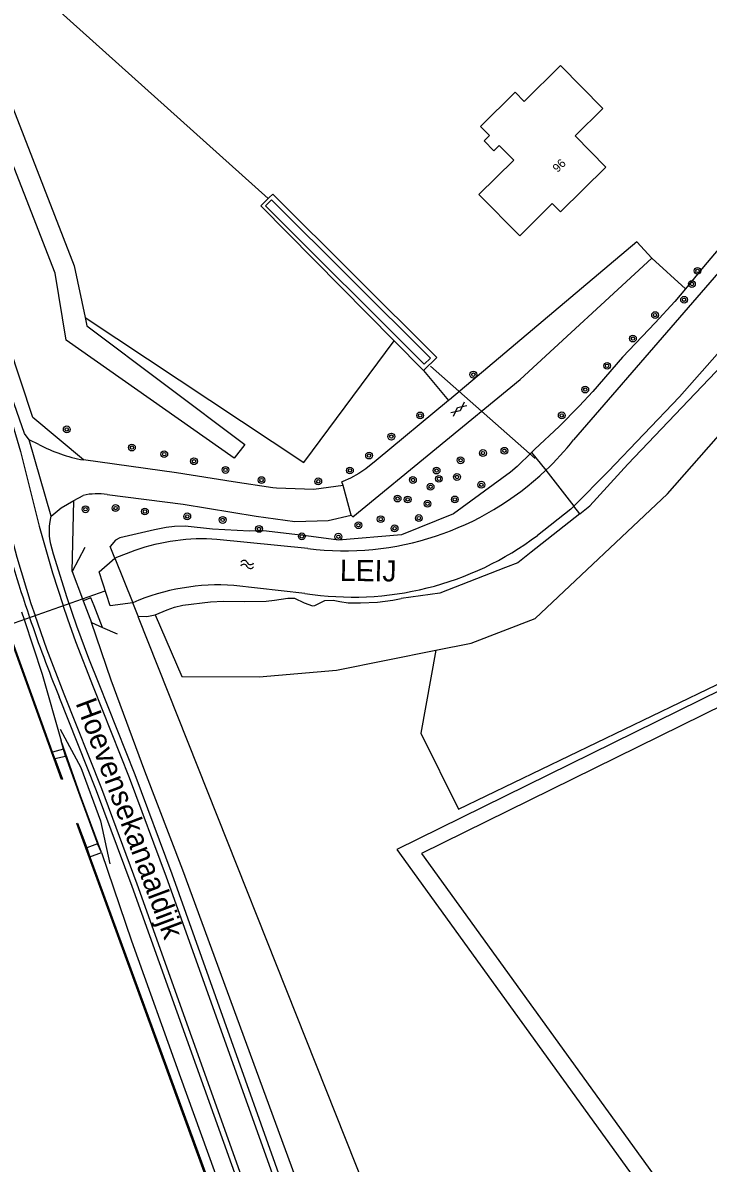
# Model space of a CAD drawing. Extents: x 135990 to 139000, y 393500 to 396000.
# Drawn here: x 136194.1 to 136274.9, y 395713.3 to 395847.7 of the extents above; entities that cross this region are included whole.
import ezdxf

# ---------------------------------------------------------------- set-up
doc = ezdxf.new("R2010")
doc.units = 0
for name, color, linetype in [('gg-afsc-hekwerk', 7, 'Continuous'), ('gg-afsc-muur', 7, 'Continuous'), ('gg-anno-huisnummerreeks BGT', 7, 'Continuous'), ('gg-anno-naam water', 7, 'Continuous'), ('gg-anno-openbare ruimte label', 7, 'Continuous'), ('gg-bbg-hoofdgebouw', 7, 'Continuous'), ('gg-knt-bovenkant onderkant talud', 7, 'Continuous'), ('gg-knt-bronhoudergrens', 7, 'Continuous'), ('gg-knt-verharding', 7, 'Continuous'), ('gg-knt-verharding nz', 7, 'Continuous'), ('gg-kntw-bovenkant insteek waterloop', 7, 'Continuous'), ('gg-kntw-waterlijn', 7, 'Continuous'), ('gg-kwrk-duiker nz buis', 7, 'Continuous'), ('gt-grn-groengrens', 7, 'Continuous'), ('gt-symb-boom', 7, 'Continuous'), ('gt-symb-gesloten verharding', 7, 'Continuous'), ('gt-symb-watersymbool', 7, 'Continuous'), ('gx-grn-maaiveld', 7, 'Continuous')]:
    doc.layers.add(name, color=color, linetype=linetype)

# ---------------------------------------------------------------- blocks, each defined once
blk = doc.blocks.new('gt0-BOOM')
at = {"layer": 'gt-symb-boom'}
for radius in [0.4, 0.2]:
    blk.add_circle((0, 0), radius, dxfattribs=at)
blk = doc.blocks.new('gt0-GESVH1')
at = {"layer": 'gt-symb-gesloten verharding'}
for p, q in [((-0.99, -0.26), (0.01, 0.24)), ((0.01, -0.26), (-0.99, 0.24)), ((0.01, 0.24), (1.01, -0.26)), ((1.01, 0.24), (0.01, -0.26))]:
    blk.add_line(p, q, dxfattribs=at)
blk = doc.blocks.new('gt0-WA')
at = {"layer": 'gt-symb-watersymbool'}
for centre, start, end in [((-0.32, 0.02), 28.0725, 151.9275), ((0.43, 0.42), 208.0725, 331.9275), ((-0.32, -0.43), 28.0725, 151.9275), ((0.43, -0.03), 208.0725, 331.9275)]:
    blk.add_arc(centre, 0.425, start, end, dxfattribs=at)

msp = doc.modelspace()

# ---------------------------------------------------------------- linework, layer by layer
at = {"layer": 'gg-afsc-hekwerk'}
for p, q in [((136201.427, 395785.836), (136199.906, 395783.029)), ((136199.906, 395783.029), (136201.129, 395779.798)), ((136199.906, 395783.029), (136201.129, 395779.798)), ((136201.129, 395779.798), (136201.228, 395779.538)), ((136201.129, 395779.798), (136201.228, 395779.538)), ((136201.228, 395779.538), (136202.196, 395776.981)), ((136202.196, 395776.981), (136203.482, 395776.416)), ((136202.196, 395776.981), (136203.482, 395776.416)), ((136203.482, 395776.416), (136205.21, 395775.656))]:
    msp.add_line(p, q, dxfattribs=at)
msp.add_lwpolyline([(136198.493, 395764.421), (136200.941, 395759.895), (136203.276, 395753.629), (136204.365, 395748.54)], dxfattribs=at)
at = {"layer": 'gg-afsc-muur'}
msp.add_line((136204.961, 395784.588), (136207.057, 395779.333), dxfattribs=at)
at = {"layer": 'gg-bbg-hoofdgebouw'}
msp.add_lwpolyline([(136248.077, 395835.46), (136252.165, 395839.498), (136253.221, 395838.43), (136257.49, 395842.675), (136262.501, 395837.597), (136259.215, 395834.354), (136262.843, 395830.681), (136257.497, 395825.405), (136256.523, 395826.382), (136252.687, 395822.571), (136247.885, 395827.441), (136252.008, 395831.49), (136250.285, 395833.229), (136249.652, 395832.602), (136248.507, 395833.769), (136249.135, 395834.391), (136248.077, 395835.46)], dxfattribs=at)
at = {"layer": 'gg-knt-bovenkant onderkant talud'}
msp.add_line((136199.906, 395783.029), (136200.101, 395791.389), dxfattribs=at)
for points in [[(136201.244, 395796.154), (136195.273, 395801.183), (136192.468, 395809.72), (136176.417, 395851.255), (136158.526, 395900.168), (136141.395, 395948.185), (136130.007, 395978.958)], [(136249.062, 395655.202), (136232.635, 395694.301), (136212.963, 395747.797), (136208.496, 395759.474), (136204.504, 395770.218), (136202.196, 395776.981)]]:
    msp.add_lwpolyline(points, dxfattribs=at)
at = {"layer": 'gg-knt-bronhoudergrens'}
msp.add_line((136191.248, 395855.527), (136223.025, 395826.98), dxfattribs=at)
for points in [[(136201.434, 395812.944), (136227.231, 395795.863), (136237.869, 395810.202)], [(136242.796, 395773.719), (136246.968, 395774.553), (136254.509, 395777.464), (136270.119, 395792.148), (136287.348, 395811.748)], [(136242.796, 395773.719), (136241.05, 395763.965), (136245.473, 395754.982), (136320.519, 395791.13)], [(136209.693, 395777.907), (136212.853, 395770.62), (136221.965, 395770.584), (136226.529, 395770.981), (136231.093, 395771.378), (136242.796, 395773.719)]]:
    msp.add_lwpolyline(points, dxfattribs=at)
at = {"layer": 'gg-knt-verharding'}
for p, q in [((136195.981, 395797.97), (136194.84, 395798.55)), ((136231.863, 395793.154), (136231.717, 395793.584)), ((136232.832, 395789.659), (136231.863, 395793.154)), ((136200.101, 395791.389), (136201.233, 395791.976)), ((136232.832, 395789.659), (136233.002, 395789.452))]:
    msp.add_line(p, q, dxfattribs=at)
for points in [[(136194.84, 395798.55), (136194.304, 395799.262), (136191.281, 395807.835), (136175.523, 395851.013), (136140.515, 395947.835), (136125.623, 395988.445)], [(136268.273, 395819.957), (136266.5, 395821.879), (136244.401, 395803.251), (136244.305, 395803.171)], [(136233.002, 395789.452), (136252.75, 395805.638), (136268.273, 395819.957)], [(136244.305, 395803.171), (136235.76, 395796.082), (136234.529, 395795.127), (136233.707, 395794.558), (136232.739, 395794.007), (136231.828, 395793.61), (136231.717, 395793.584)], [(136224.004, 395792.838), (136223.571, 395792.853), (136218.893, 395793.581), (136212.228, 395794.652), (136201.244, 395796.154)], [(136231.863, 395793.154), (136228.41, 395792.682), (136224.004, 395792.838)], [(136197.449, 395789.539), (136198.629, 395790.531), (136200.101, 395791.389)], [(136204.043, 395792.076), (136213.004, 395790.931), (136221.629, 395789.529), (136226.189, 395788.889), (136230.119, 395789.015), (136232.832, 395789.659)], [(136203.093, 395769.73), (136201.887, 395772.749), (136200.474, 395776.558), (136199.334, 395779.89), (136197.739, 395785.068), (136197.418, 395786.215), (136197.333, 395786.64), (136197.262, 395787.176), (136197.233, 395787.825), (136197.256, 395788.366), (136197.318, 395788.903), (136197.399, 395789.328), (136197.449, 395789.539)], [(136244.295, 395656.286), (136230.86, 395693.582), (136211.713, 395747.336), (136207.367, 395759.044), (136203.093, 395769.73)], [(136255.708, 395609.808), (136239.744, 395654.526), (136226.317, 395691.893), (136206.997, 395745.883), (136202.792, 395757.151), (136198.369, 395768.24)]]:
    msp.add_lwpolyline(points, dxfattribs=at)
for centre, radius, start, end in [((136204.751, 395814.854), 19.026, 242.54952, 259.37645), ((136202.886, 395785.05), 7.121, 80.65151, 103.42476), ((136373.454, 395838.52), 188.663, 194.92704, 198.83878), ((136373.233, 395838.428), 188.424, 198.83382, 201.86986)]:
    msp.add_arc(centre, radius, start, end, dxfattribs=at)
at = {"layer": 'gg-knt-verharding nz'}
msp.add_line((136197.449, 395789.539), (136194.84, 395798.55), dxfattribs=at)
for points in [[(136116.757, 396000), (136121.671, 395987.179), (136136.571, 395946.56), (136153.867, 395898.856), (136171.516, 395849.993), (136187.438, 395805.778), (136189.89, 395798.04), (136191.937, 395790.186), (136193.392, 395784.681), (136195.054, 395779.234), (136195.542, 395777.827)], [(136120.537, 396000), (136125.042, 395988.226), (136139.915, 395947.719), (136157.35, 395899.595), (136190.76, 395807.111), (136192.059, 395803.156), (136193.814, 395797.163), (136196.045, 395788.338), (136197.62, 395782.842), (136198.877, 395779.004)], [(136256.275, 395610.025), (136240.32, 395654.726), (136226.925, 395692.057), (136207.584, 395746.156), (136203.424, 395757.41), (136198.987, 395768.549), (136196.919, 395773.855), (136195.542, 395777.827)], [(136259.572, 395611.284), (136243.654, 395655.964), (136230.221, 395693.319), (136211.055, 395746.99), (136206.688, 395758.699), (136202.442, 395769.391), (136200.364, 395774.717), (136199.399, 395777.408), (136198.877, 395779.004)]]:
    msp.add_lwpolyline(points, dxfattribs=at)
at = {"layer": 'gg-kntw-bovenkant insteek waterloop'}
for p, q in [((136237.869, 395810.202), (136241.337, 395806.692)), ((136220.261, 395798), (136219.003, 395796.356))]:
    msp.add_line(p, q, dxfattribs=at)
for points in [[(136332.359, 395875.615), (136329.962, 395873.177), (136323.008, 395866.952), (136318.207, 395862.493), (136316.111, 395860.371), (136309.067, 395853.686), (136301.51, 395846.687), (136295.745, 395842.008), (136293.093, 395839.723), (136290.454, 395836.727), (136287.413, 395833.419), (136284.119, 395830.106), (136275.654, 395820.442), (136274.363, 395818.915), (136272.255, 395816.315)], [(136219.003, 395796.356), (136199.198, 395810.289), (136197.929, 395818.163), (136186.924, 395846.364), (136186.411, 395848.506), (136187.663, 395849.065)], [(136188.363, 395849.377), (136189.262, 395846.982), (136200.173, 395819.057), (136201.434, 395812.944)], [(136223.025, 395826.98), (136222.147, 395826.112), (136237.869, 395810.202)], [(136241.337, 395806.692), (136242.898, 395808.235), (136223.584, 395827.504), (136223.133, 395827.086), (136223.025, 395826.98)], [(136201.434, 395812.944), (136201.636, 395811.964), (136220.261, 395798)], [(136312.713, 395786.068), (136312.21, 395786.661), (136238.189, 395750.233), (136287.33, 395682.257), (136289.018, 395683.478)], [(136312.713, 395786.068), (136312.541, 395784.933), (136241.094, 395749.771), (136289.018, 395683.478)], [(136209.693, 395777.907), (136211.107, 395778.49), (136211.989, 395778.807), (136212.959, 395779.032), (136216.244, 395779.44), (136217.767, 395779.498), (136220.288, 395779.473), (136222.791, 395779.522), (136223.787, 395779.612), (136225.337, 395779.876), (136226.131, 395779.85), (136227.289, 395779.299), (136228.269, 395778.977), (136228.548, 395779.001), (136229.704, 395779.608), (136230.679, 395779.635), (136231.466, 395779.461), (136232.475, 395779.33), (136233.932, 395779.316), (136235.93, 395779.398), (136237.74, 395779.623), (136238.72, 395779.824)], [(136207.685, 395777.758), (136208.721, 395777.691), (136209.693, 395777.907)]]:
    msp.add_lwpolyline(points, dxfattribs=at)
at = {"layer": 'gg-kntw-waterlijn'}
for p, q in [((136223.427, 395826.815), (136242.164, 395808.152)), ((136227.713, 395785.706), (136216.995, 395786.794)), ((136207.324, 395785.481), (136204.961, 395784.588)), ((136227.362, 395780.43), (136218.999, 395781.372))]:
    msp.add_line(p, q, dxfattribs=at)
for points in [[(136334.154, 395875.239), (136314.263, 395856.43), (136289.01, 395832.551), (136283.009, 395826.197), (136259.042, 395798.523)], [(136223.427, 395826.815), (136222.699, 395826.125), (136241.437, 395807.461), (136242.164, 395808.152)]]:
    msp.add_lwpolyline(points, dxfattribs=at)
for centre, radius, start, end in [((136233.002, 395816.22), 36.231, 261.04453, 306.96306), ((136215.305, 395762.967), 23.887, 85.94352, 109.51966), ((136217.274, 395755.482), 25.947, 86.18911, 113.1896)]:
    msp.add_arc(centre, radius, start, end, dxfattribs=at)
at = {"layer": 'gg-kwrk-duiker nz buis'}
for p, q in [((136242.168, 395807.214), (136254.528, 395796.344)), ((136157.059, 395764.251), (136203.824, 395780.749))]:
    msp.add_line(p, q, dxfattribs=at)
at = {"layer": 'gt-grn-groengrens'}
for p, q in [((136272.255, 395816.315), (136268.273, 395819.957)), ((136241.337, 395806.692), (136244.305, 395803.171))]:
    msp.add_line(p, q, dxfattribs=at)
msp.add_lwpolyline([(136203.482, 395776.416), (136202.523, 395778.949), (136202.134, 395779.901), (136201.228, 395779.538)], dxfattribs=at)
at = {"layer": 'gx-grn-maaiveld'}
for p, q in [((136254.088, 395797.055), (136255.754, 395794.936)), ((136255.754, 395794.936), (136259.078, 395790.707)), ((136259.773, 395789.823), (136259.078, 395790.707)), ((136204.961, 395784.588), (136204.42, 395785.945)), ((136207.685, 395777.758), (136207.057, 395779.333)), ((136193.954, 395778.25), (136194.246, 395777.37)), ((136197.61, 395761.726), (136192.203, 395776.649)), ((136207.756, 395777.581), (136207.685, 395777.758)), ((136255.405, 395657.603), (136207.756, 395777.581)), ((136198.905, 395762.047), (136198.608, 395763.049)), ((136198.905, 395762.047), (136197.61, 395761.726)), ((136197.888, 395760.959), (136197.61, 395761.726)), ((136199.147, 395761.233), (136198.905, 395762.047)), ((136197.888, 395760.959), (136199.147, 395761.233)), ((136202.907, 395750.895), (136201.635, 395750.421)), ((136201.635, 395750.421), (136202.014, 395749.383)), ((136202.014, 395749.383), (136203.392, 395749.871)), ((136203.392, 395749.871), (136202.907, 395750.895))]:
    msp.add_line(p, q, dxfattribs=at)
for points in [[(136259.078, 395790.707), (136263.121, 395794.803), (136271.516, 395803.601), (136287.215, 395821.374), (136304.092, 395838.448), (136322.089, 395856.212), (136330.973, 395864.357), (136338.692, 395871.621)], [(136259.773, 395789.823), (136260.953, 395790.755), (136265.427, 395795.677), (136275.005, 395805.691), (136287.406, 395818.658), (136290.495, 395821.887), (136302.319, 395833.404), (136309.95, 395840.835), (136319.24, 395849.883), (136322.115, 395852.683), (136326.958, 395857.4), (136335.346, 395865.57), (136340.079, 395870.179)], [(136272.255, 395816.315), (136270.989, 395814.842), (136268.679, 395812.316), (136264.79, 395808.259), (136261.313, 395804.24), (136259.689, 395802.488), (136257.328, 395800.116), (136254.479, 395797.438), (136254.088, 395797.055)], [(136254.088, 395797.055), (136252.371, 395795.37), (136251.619, 395794.713), (136244.866, 395789.796), (136238.754, 395787.335), (136231.309, 395786.71), (136227.501, 395787.201), (136222.482, 395787.812), (136220.842, 395787.77), (136216.461, 395788), (136213.252, 395788.364), (136211.98, 395788.328), (136210.986, 395788.185), (136209.628, 395787.909), (136205.527, 395786.971), (136205.026, 395786.691), (136204.42, 395785.945)], [(136259.078, 395790.707), (136258.735, 395790.359), (136254.788, 395787.27)], [(136259.773, 395789.823), (136254.039, 395785.297), (136252.451, 395784.043), (136250.999, 395783.477), (136243.279, 395780.464), (136238.72, 395779.824)], [(136207.057, 395779.333), (136204.411, 395778.976), (136203.091, 395782.983), (136204.961, 395784.588)], [(136197.888, 395760.959), (136198.769, 395758.529), (136198.675, 395758.495), (136191.818, 395777.417)], [(136194.246, 395777.37), (136196.392, 395770.915), (136198.608, 395763.049)], [(136203.392, 395749.871), (136200.905, 395756.585), (136198.608, 395763.049)], [(136199.147, 395761.233), (136200.811, 395756.551), (136202.907, 395750.895)], [(136274.37, 395550.499), (136267.142, 395569.642), (136260.263, 395588.766), (136254.957, 395603.355), (136247.334, 395624.422), (136240.154, 395644.264), (136235.242, 395657.663), (136216.831, 395708.546), (136200.473, 395753.309), (136200.567, 395753.343), (136201.635, 395750.421)], [(136203.392, 395749.871), (136206.925, 395739.488), (136212.689, 395723.375), (136218.301, 395707.836), (136224.046, 395692.753), (136229.432, 395677.549), (136234.478, 395663.462), (136240.048, 395648.769), (136245.336, 395633.92), (136249.682, 395621.185), (136254.063, 395609.18)], [(136202.014, 395749.383), (136216.925, 395708.58), (136235.336, 395657.697), (136240.248, 395644.298), (136253.09, 395608.808)]]:
    msp.add_lwpolyline(points, dxfattribs=at)
for centre, radius, start, end in [((136231.85, 395820.148), 34.742, 313.47459, 321.50596), ((136231.946, 395820.055), 34.609, 262.97438, 313.46466)]:
    msp.add_arc(centre, radius, start, end, dxfattribs=at)

# ---------------------------------------------------------------- block references
at = {"layer": 'gt-symb-boom'}
for p in [(136273.652, 395818.448), (136272.99, 395816.902), (136272.068, 395815.039), (136268.648, 395813.233), (136266.033, 395810.469), (136262.996, 395807.252), (136247.224, 395806.215), (136260.413, 395804.453), (136240.948, 395801.41), (136257.645, 395801.413), (136199.284, 395799.765), (136237.553, 395798.909), (136206.961, 395797.62), (136210.779, 395796.845), (136234.927, 395796.672), (136248.356, 395796.975), (136250.883, 395797.243), (136214.284, 395796.006), (136217.999, 395794.98), (136232.665, 395794.92), (136242.883, 395794.908), (136245.717, 395796.12), (136222.242, 395793.784), (136228.936, 395793.637), (136240.099, 395793.798), (136243.157, 395793.93), (136245.291, 395794.15), (136242.181, 395793), (136248.162, 395793.242), (136238.288, 395791.608), (136239.476, 395791.502), (136241.818, 395790.996), (136245.039, 395791.507), (136201.496, 395790.344), (136205.035, 395790.489), (136208.498, 395790.08), (136213.486, 395789.507), (136217.666, 395789.085), (136233.67, 395788.466), (136236.3, 395789.18), (136240.796, 395789.31), (136221.951, 395788.032), (136226.996, 395787.155), (136231.309, 395787.11), (136237.931, 395788.096)]:
    msp.add_blockref('gt0-BOOM', p, dxfattribs=at)
at = {"layer": 'gt-symb-gesloten verharding', "rotation": -140.6420430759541}
msp.add_blockref('gt0-GESVH1', (136245.522, 395802.149), dxfattribs=at)
at = {"layer": 'gt-symb-watersymbool', "rotation": -3.1543921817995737}
msp.add_blockref('gt0-WA', (136220.5, 395783.847), dxfattribs=at)

# ---------------------------------------------------------------- texts
at = {"layer": 'gg-anno-huisnummerreeks BGT'}
msp.add_text('96', height=1, rotation=44.6, dxfattribs=at).set_placement((136257.158, 395829.988))
at = {"layer": 'gg-anno-naam water'}
msp.add_text('LEIJ', height=2.5, rotation=359.31248, dxfattribs=at).set_placement((136231.47, 395781.905))
at = {"layer": 'gg-anno-openbare ruimte label'}
msp.add_text('Hoevensekanaaldijk', height=2.5, rotation=290.6, dxfattribs=at).set_placement((136200.29, 395767.504))

doc.saveas('drawing.dxf')
